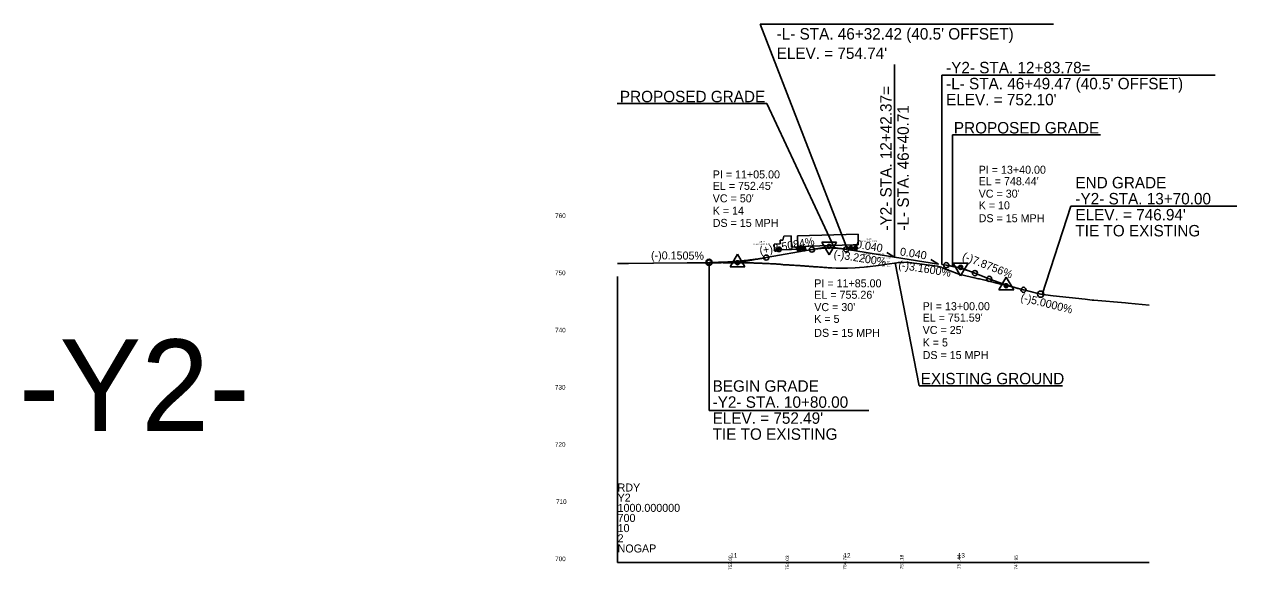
# Model space of a CAD drawing. Extents: x 1554255 to 1803987, y 659549 to 692876.
# Drawn here: x 1554284 to 1555344, y 690303 to 690780 of the extents above; entities that cross this region are included whole.
import ezdxf

# ---------------------------------------------------------------- set-up
doc = ezdxf.new("R2010")
doc.units = 0
for name, color, linetype in [('Default', 7, 'Continuous'), ('Exist Profile Cell', 7, 'Continuous'), ('Exist Vertical Profile Ground Line', 7, 'Continuous'), ('Exist Vertical Profile Vertical Axis Label', 7, 'Continuous'), ('Prop PFL Text', 7, 'Continuous'), ('Prop PFL VPI Symbol CELL', 7, 'Continuous'), ('Prop Vertical Profile Curve Label', 7, 'Continuous'), ('Prop Vertical Profile Grade', 7, 'Continuous'), ('Prop Vertical Profile Grade Label', 7, 'Continuous'), ('Prop Vertical Profile Strip Grade', 7, 'Continuous'), ('Prop VPI Label', 7, 'Continuous'), ('Scratch_Level_0', 7, 'Continuous')]:
    doc.layers.add(name, color=color, linetype=linetype)

msp = doc.modelspace()

# ---------------------------------------------------------------- linework, layer by layer
at = {"layer": 'Exist Profile Cell'}
for q in [(1554802.9, 690559.3), (1555267.8, 690309.3), (1554802.9, 690309.3)]:
    msp.add_line((1554802.9, 690309.3), q, dxfattribs=at)
at = {"layer": 'Exist Vertical Profile Ground Line'}
msp.add_lwpolyline([(1554802.9, 690570.7), (1554811.8, 690570.7), (1554812.3, 690570.7), (1554833.8, 690571), (1554834.2, 690571), (1554863.6, 690571.3), (1554864.4, 690571.3), (1554871.1, 690571.3), (1554878.4, 690571.3), (1554879.3, 690571.4), (1554880.3, 690571.4), (1554881.2, 690571.4), (1554882.2, 690571.4), (1554883.1, 690571.4), (1554884.1, 690571.4), (1554885, 690571.4), (1554886, 690571.4), (1554886.9, 690571.4), (1554887.9, 690571.4), (1554888.8, 690571.4), (1554889.8, 690571.4), (1554890.7, 690571.4), (1554891.7, 690571.4), (1554892.7, 690571.4), (1554893.6, 690571.4), (1554894.6, 690571.5), (1554895.5, 690571.4), (1554896.5, 690571.4), (1554897.4, 690571.4), (1554898.4, 690571.4), (1554899.3, 690571.4), (1554900.3, 690571.4), (1554901.2, 690571.4), (1554902.2, 690571.4), (1554903.1, 690571.4), (1554904.1, 690571.4), (1554905, 690571.4), (1554906, 690571.4), (1554906.9, 690571.4), (1554907.9, 690571.4), (1554908.8, 690571.4), (1554909.8, 690571.4), (1554910.8, 690571.4), (1554911.7, 690571.4), (1554912.7, 690571.4), (1554913.6, 690571.4), (1554914.6, 690571.4), (1554914.9, 690571.4), (1554915.5, 690571.3), (1554916.5, 690571.3), (1554917.4, 690571.3), (1554918.4, 690571.3), (1554919.3, 690571.3), (1554920.3, 690571.2), (1554920.6, 690571.2), (1554921.5, 690571.2), (1554922.2, 690571.1), (1554923.1, 690571.1), (1554924.1, 690571.1), (1554925, 690571), (1554926, 690571), (1554927, 690571), (1554927.9, 690570.9), (1554928.9, 690570.9), (1554929.8, 690570.8), (1554930.8, 690570.8), (1554931.7, 690570.8), (1554932.7, 690570.7), (1554933.6, 690570.7), (1554934.6, 690570.6), (1554935.5, 690570.6), (1554936.5, 690570.5), (1554937.4, 690570.5), (1554938.4, 690570.4), (1554939.3, 690570.4), (1554940.3, 690570.3), (1554941.2, 690570.3), (1554942.2, 690570.2), (1554943.1, 690570.1), (1554944.1, 690570.1), (1554945.1, 690570), (1554946, 690569.9), (1554946.5, 690569.8), (1554947, 690569.8), (1554947.9, 690569.7), (1554948.9, 690569.6), (1554949.2, 690569.6), (1554949.8, 690569.6), (1554950.8, 690569.5), (1554951.7, 690569.5), (1554952.7, 690569.5), (1554953.6, 690569.4), (1554954.6, 690569.4), (1554955.5, 690569.3), (1554956.5, 690569.3), (1554957.4, 690569.2), (1554958.4, 690569.1), (1554959.3, 690569.1), (1554960.3, 690569), (1554961.3, 690569), (1554962.2, 690568.9), (1554963.2, 690568.8), (1554964.1, 690568.8), (1554965.1, 690568.7), (1554966, 690568.6), (1554967, 690568.5), (1554967.9, 690568.5), (1554968.9, 690568.4), (1554969.8, 690568.3), (1554970.8, 690568.2), (1554971.2, 690568.1), (1554971.7, 690568.1), (1554972.7, 690568), (1554973.6, 690568), (1554974.6, 690567.9), (1554975.1, 690567.9), (1554975.5, 690567.8), (1554976.5, 690567.8), (1554977.4, 690567.7), (1554978.4, 690567.7), (1554979.4, 690567.6), (1554980.3, 690567.5), (1554981.3, 690567.5), (1554982.2, 690567.4), (1554983.2, 690567.3), (1554984.1, 690567.2), (1554985.1, 690567.2), (1554986, 690567.1), (1554987, 690567), (1554987.9, 690567), (1554990.2, 690566.8), (1554994, 690566.7), (1554999.4, 690566.6), (1555004, 690566.7), (1555010.7, 690566.9), (1555014.4, 690567.1), (1555018.6, 690567.4), (1555021.5, 690567.7), (1555031.2, 690569.1), (1555034.5, 690569.6), (1555036.2, 690569.9), (1555045.2, 690571.1), (1555047, 690571.3), (1555048.3, 690571.5), (1555053.3, 690571.6), (1555056.5, 690571.8), (1555056.9, 690571.7), (1555057.8, 690571.6), (1555082.8, 690568.5), (1555086.1, 690567.4), (1555086.8, 690567), (1555093.9, 690564.4), (1555099.9, 690562), (1555101.4, 690561.4), (1555117.3, 690557.6), (1555118.5, 690557.4), (1555119.3, 690557.3), (1555143.7, 690551.2), (1555145.7, 690550.8), (1555174.3, 690543.6), (1555174.8, 690543.5), (1555177, 690543.3), (1555183.9, 690542.5), (1555211.7, 690539.4), (1555213.9, 690539.2), (1555217.9, 690538.8), (1555219.4, 690538.6), (1555247.2, 690536.2), (1555249.4, 690536), (1555267.8, 690534.4)], dxfattribs=at)
at = {"layer": 'Prop PFL Text'}
for p, q in [((1554927.7, 690779.9), (1555184, 690779.9)), ((1555003.9, 690583), (1554927.7, 690779.9)), ((1555045.2, 690576.4), (1555045.2, 690744.6)), ((1555325.4, 690735.3), (1555086.6, 690735.3)), ((1555086.6, 690569.8), (1555086.6, 690735.3)), ((1554933.3, 690710.5), (1554802.6, 690710.5)), ((1554992.6, 690584.2), (1554933.3, 690710.5)), ((1555225.3, 690683.2), (1555095.7, 690683.2)), ((1555095.7, 690568.2), (1555095.7, 690683.2)), ((1555174.3, 690543.6), (1555199.3, 690620.7)), ((1555344.4, 690620.7), (1555199.3, 690620.7)), ((1554882.9, 690571.7), (1554882.9, 690442.2)), ((1555045.6, 690571.2), (1555066.7, 690463.9)), ((1555192, 690463.9), (1555066.7, 690463.9)), ((1554882.9, 690442.2), (1555022.5, 690442.2))]:
    msp.add_line(p, q, dxfattribs=at)
at = {"layer": 'Prop PFL VPI Symbol CELL'}
for p, q in [((1554987.9, 690578.2), (1554981.4, 690589.4)), ((1554994.4, 690589.4), (1554981.4, 690589.4)), ((1554987.9, 690578.2), (1554994.4, 690589.4)), ((1554907.8, 690578.9), (1554901.4, 690567.7)), ((1554907.8, 690578.9), (1554914.3, 690567.7)), ((1555102.9, 690559.8), (1555096.4, 690571)), ((1555109.4, 690571), (1555096.4, 690571)), ((1555102.9, 690559.8), (1555109.4, 690571)), ((1554901.4, 690567.7), (1554914.3, 690567.7)), ((1555142.8, 690558.8), (1555136.4, 690547.6)), ((1555142.8, 690558.8), (1555149.3, 690547.6)), ((1555136.4, 690547.6), (1555149.3, 690547.6))]:
    msp.add_line(p, q, dxfattribs=at)
for centre, radius in [((1554987.9, 690585.7), 1.75), ((1554987.9, 690585.7), 1.2), ((1554907.8, 690571.4), 1.75), ((1554907.8, 690571.4), 1.2), ((1555102.9, 690567.3), 1.75), ((1555102.9, 690567.3), 1.2), ((1555142.8, 690551.3), 1.75), ((1555142.8, 690551.3), 1.2)]:
    msp.add_circle(centre, radius, dxfattribs=at)
at = {"layer": 'Prop Vertical Profile Curve Label'}
for centre in [(1554972.9, 690582.9), (1555002.9, 690583.1), (1554882.9, 690571.7), (1554932.9, 690575.9), (1555090.4, 690569.2), (1555115.4, 690562.3), (1555127.9, 690557.3), (1555157.9, 690547.7)]:
    msp.add_circle(centre, 2.25, dxfattribs=at)
at = {"layer": 'Prop Vertical Profile Grade'}
for p, q in [((1554932.9, 690575.9), (1554972.9, 690582.9)), ((1555002.9, 690583.1), (1555003.9, 690583)), ((1555086.6, 690569.8), (1555090.4, 690569.2)), ((1555115.4, 690562.3), (1555127.9, 690557.3)), ((1555157.9, 690547.7), (1555172.9, 690543.9))]:
    msp.add_line(p, q, dxfattribs=at)
for points in [[(1554972.9, 690582.9), (1554973.5, 690583), (1554974.1, 690583.1), (1554974.7, 690583.2), (1554975.3, 690583.3), (1554975.9, 690583.4), (1554976.5, 690583.5), (1554977.1, 690583.5), (1554977.7, 690583.6), (1554978.3, 690583.7), (1554978.9, 690583.8), (1554979.5, 690583.8), (1554980.1, 690583.9), (1554980.7, 690583.9), (1554981.3, 690584), (1554981.9, 690584), (1554982.5, 690584.1), (1554983.1, 690584.1), (1554983.7, 690584.1), (1554984.3, 690584.2), (1554984.9, 690584.2), (1554985.5, 690584.2), (1554986.1, 690584.2), (1554986.7, 690584.3), (1554987.3, 690584.3), (1554987.9, 690584.3), (1554988.5, 690584.3), (1554989.1, 690584.3), (1554989.7, 690584.3), (1554990.3, 690584.3), (1554990.9, 690584.2), (1554991.5, 690584.2), (1554992.1, 690584.2), (1554992.7, 690584.2), (1554993.3, 690584.1), (1554993.9, 690584.1), (1554994.5, 690584.1), (1554995.1, 690584), (1554995.7, 690584), (1554996.3, 690583.9), (1554996.9, 690583.9), (1554997.5, 690583.8), (1554998.1, 690583.8), (1554998.7, 690583.7), (1554999.3, 690583.6), (1554999.9, 690583.6), (1555000.5, 690583.5), (1555001.1, 690583.4), (1555001.7, 690583.3), (1555002.3, 690583.2), (1555002.9, 690583.1)], [(1554882.9, 690571.7), (1554883.9, 690571.7), (1554884.9, 690571.7), (1554885.9, 690571.7), (1554886.9, 690571.7), (1554887.9, 690571.7), (1554888.9, 690571.7), (1554889.9, 690571.7), (1554890.9, 690571.7), (1554891.9, 690571.8), (1554892.9, 690571.8), (1554893.9, 690571.8), (1554894.9, 690571.9), (1554895.9, 690571.9), (1554896.9, 690571.9), (1554897.9, 690572), (1554898.9, 690572), (1554899.9, 690572.1), (1554900.9, 690572.1), (1554901.9, 690572.2), (1554902.9, 690572.3), (1554903.9, 690572.3), (1554904.9, 690572.4), (1554905.9, 690572.5), (1554906.9, 690572.6), (1554907.9, 690572.6), (1554908.9, 690572.7), (1554909.9, 690572.8), (1554910.9, 690572.9), (1554911.9, 690573), (1554912.9, 690573.1), (1554913.9, 690573.2), (1554914.9, 690573.3), (1554915.9, 690573.4), (1554916.9, 690573.5), (1554917.9, 690573.7), (1554918.9, 690573.8), (1554919.9, 690573.9), (1554920.9, 690574), (1554921.9, 690574.2), (1554922.9, 690574.3), (1554923.9, 690574.5), (1554924.9, 690574.6), (1554925.9, 690574.7), (1554926.9, 690574.9), (1554927.9, 690575.1), (1554928.9, 690575.2), (1554929.9, 690575.4), (1554930.9, 690575.5), (1554931.9, 690575.7), (1554932.9, 690575.9)], [(1555090.4, 690569.2), (1555090.9, 690569.1), (1555091.4, 690569), (1555091.9, 690568.9), (1555092.4, 690568.8), (1555092.9, 690568.7), (1555093.4, 690568.7), (1555093.9, 690568.6), (1555094.4, 690568.5), (1555094.9, 690568.4), (1555095.4, 690568.3), (1555095.9, 690568.2), (1555096.4, 690568.1), (1555096.9, 690567.9), (1555097.4, 690567.8), (1555097.9, 690567.7), (1555098.4, 690567.6), (1555098.9, 690567.5), (1555099.4, 690567.4), (1555099.9, 690567.2), (1555100.4, 690567.1), (1555100.9, 690567), (1555101.4, 690566.9), (1555101.9, 690566.7), (1555102.4, 690566.6), (1555102.9, 690566.5), (1555103.4, 690566.3), (1555103.9, 690566.2), (1555104.4, 690566), (1555104.9, 690565.9), (1555105.4, 690565.7), (1555105.9, 690565.6), (1555106.4, 690565.4), (1555106.9, 690565.3), (1555107.4, 690565.1), (1555107.9, 690565), (1555108.4, 690564.8), (1555108.9, 690564.6), (1555109.4, 690564.5), (1555109.9, 690564.3), (1555110.4, 690564.1), (1555110.9, 690563.9), (1555111.4, 690563.8), (1555111.9, 690563.6), (1555112.4, 690563.4), (1555112.9, 690563.2), (1555113.4, 690563), (1555113.9, 690562.9), (1555114.4, 690562.7), (1555114.9, 690562.5), (1555115.4, 690562.3)], [(1555127.9, 690557.3), (1555128.5, 690557.1), (1555129.1, 690556.9), (1555129.7, 690556.6), (1555130.3, 690556.4), (1555130.9, 690556.2), (1555131.5, 690556), (1555132.1, 690555.7), (1555132.7, 690555.5), (1555133.3, 690555.3), (1555133.9, 690555.1), (1555134.5, 690554.9), (1555135.1, 690554.6), (1555135.7, 690554.4), (1555136.3, 690554.2), (1555136.9, 690554), (1555137.5, 690553.8), (1555138.1, 690553.6), (1555138.7, 690553.4), (1555139.3, 690553.2), (1555139.9, 690553), (1555140.5, 690552.8), (1555141.1, 690552.6), (1555141.7, 690552.4), (1555142.3, 690552.2), (1555142.9, 690552), (1555143.5, 690551.8), (1555144.1, 690551.6), (1555144.7, 690551.4), (1555145.3, 690551.2), (1555145.9, 690551), (1555146.5, 690550.9), (1555147.1, 690550.7), (1555147.7, 690550.5), (1555148.3, 690550.3), (1555148.9, 690550.1), (1555149.5, 690550), (1555150.1, 690549.8), (1555150.7, 690549.6), (1555151.3, 690549.4), (1555151.9, 690549.3), (1555152.5, 690549.1), (1555153.1, 690548.9), (1555153.7, 690548.8), (1555154.3, 690548.6), (1555154.9, 690548.5), (1555155.5, 690548.3), (1555156.1, 690548.2), (1555156.7, 690548), (1555157.3, 690547.8), (1555157.9, 690547.7)]]:
    msp.add_spline(points, degree=3, dxfattribs=at)
at = {"layer": 'Prop VPI Label'}
for p, q in [((1554972.9, 690582.9), (1554985.1, 690585.1)), ((1555002.9, 690583.1), (1554990.6, 690585.1)), ((1555006.1, 690582.6), (1555045.2, 690576.4)), ((1555045.2, 690576.4), (1555038.5, 690580.2)), ((1554882.9, 690571.7), (1554905.1, 690571.5)), ((1554932.9, 690575.9), (1554910.6, 690572)), ((1555045.2, 690576.4), (1555083.6, 690570.2)), ((1555083.6, 690570.2), (1555076.9, 690574.1)), ((1555090.4, 690569.2), (1555100.1, 690567.6)), ((1555115.4, 690562.3), (1555105.4, 690566.2)), ((1555127.9, 690557.3), (1555140.3, 690552.5)), ((1555157.9, 690547.7), (1555145.5, 690550.8))]:
    msp.add_line(p, q, dxfattribs=at)
for centre in [(1554882.9, 690571.7), (1555172.9, 690543.9)]:
    msp.add_circle(centre, 2.75, dxfattribs=at)
at = {"layer": 'Scratch_Level_0'}
for p, q in [((1554945.1, 690591.1), (1554945, 690588)), ((1554945.1, 690591.1), (1554945, 690588)), ((1554947.4, 690591.1), (1554945.1, 690591.1)), ((1554947.4, 690591.1), (1554945.1, 690591.1)), ((1554948.2, 690594.7), (1554947.4, 690591.1)), ((1554948.2, 690594.7), (1554947.4, 690591.1)), ((1554954.7, 690594.9), (1554948.2, 690594.7)), ((1554954.7, 690594.9), (1554948.2, 690594.7)), ((1554955, 690584.9), (1554954.7, 690594.9)), ((1554955, 690584.9), (1554954.7, 690594.9)), ((1555013.2, 690596.5), (1554960.2, 690595)), ((1555013.2, 690596.5), (1554960.2, 690595)), ((1554960.2, 690595), (1554960.5, 690585.5)), ((1554960.2, 690595), (1554960.5, 690585.5)), ((1555013.4, 690587), (1555013.2, 690596.5)), ((1555013.4, 690587), (1555013.2, 690596.5)), ((1554945, 690588), (1554939.9, 690587.6)), ((1554945, 690588), (1554939.9, 690587.6)), ((1554939.9, 690587.6), (1554940, 690582.5)), ((1554939.9, 690587.6), (1554940, 690582.5)), ((1554940, 690582.5), (1554941.9, 690582.5)), ((1554940, 690582.5), (1554941.9, 690582.5)), ((1554946.2, 690582.6), (1554955, 690582.9)), ((1554946.2, 690582.6), (1554955, 690582.9)), ((1554965.6, 690585.2), (1554955, 690584.9)), ((1554965.6, 690585.2), (1554955, 690584.9)), ((1554955, 690582.9), (1554965.6, 690583.2)), ((1554955, 690582.9), (1554965.6, 690583.2)), ((1554960.5, 690585.5), (1555008.9, 690586.9)), ((1554960.5, 690585.5), (1555008.9, 690586.9)), ((1554965.6, 690583.2), (1554965.6, 690585.2)), ((1554965.6, 690583.2), (1554965.6, 690585.2)), ((1555008.9, 690586.9), (1555013.4, 690587)), ((1555008.9, 690586.9), (1555013.4, 690587))]:
    msp.add_line(p, q, dxfattribs=at)
for centre, radius in [((1554944, 690582.9), 1.83), ((1554944, 690582.9), 1.83), ((1554944, 690582.9), 1.47), ((1554944, 690582.9), 1.47), ((1554944, 690582.9), 0.262), ((1554944, 690582.9), 0.262), ((1554961.4, 690583.4), 1.83), ((1554961.4, 690583.4), 1.83), ((1554961.4, 690583.4), 1.47), ((1554961.4, 690583.4), 1.47), ((1554961.4, 690583.4), 0.262), ((1554961.4, 690583.4), 0.262), ((1554965.6, 690583.5), 1.83), ((1554965.6, 690583.5), 1.83), ((1554965.6, 690583.5), 1.47), ((1554965.6, 690583.5), 1.47), ((1554965.6, 690583.5), 0.262), ((1554965.6, 690583.5), 0.262), ((1555007, 690584.1), 1.65), ((1555007, 690584.1), 1.65), ((1555007, 690584.1), 1.32), ((1555007, 690584.1), 1.32), ((1555007, 690584.1), 0.262), ((1555007, 690584.1), 0.262), ((1555011, 690584.2), 1.65), ((1555011, 690584.2), 1.65), ((1555011, 690584.2), 1.32), ((1555011, 690584.2), 1.32), ((1555011, 690584.2), 0.262), ((1555011, 690584.2), 0.262)]:
    msp.add_circle(centre, radius, dxfattribs=at)
for start, end in [(91.5652, 190.4288), (91.5652, 190.4288), (352.7015, 91.5652), (352.7015, 91.5652)]:
    msp.add_arc((1554944, 690582.9), 2.16, start, end, dxfattribs=at)

# ---------------------------------------------------------------- texts
at = {"layer": 'Default'}
for s, p in [('760', (1554748.3, 690610.5)), ('750', (1554748.2, 690560.5)), ('740', (1554748.3, 690510.5)), ('730', (1554748.1, 690460.5)), ('720', (1554748.1, 690410.5)), ('710', (1554749.1, 690360.5)), ('700', (1554748.3, 690310.5)), ('11', (1554901.5, 690313.5)), ('12', (1555000.5, 690313.5)), ('13', (1555100.5, 690313.5))]:
    msp.add_text(s, height=4, dxfattribs=at).set_placement(p)
at = {"layer": 'Exist Profile Cell'}
for s, p in [('RDY', (1554802.9, 690371.4)), ('Y2', (1554802.9, 690362.5)), ('1000.000000', (1554802.9, 690353.6)), ('700', (1554802.9, 690344.8)), ('10', (1554802.9, 690335.9)), ('2', (1554802.9, 690327)), ('NOGAP', (1554802.9, 690318.1))]:
    msp.add_text(s, height=7, dxfattribs=at).set_placement(p)
at = {"layer": 'Exist Vertical Profile Vertical Axis Label'}
msp.add_text('-Y2-', height=80, dxfattribs=at).set_placement((1554279.2, 690424.3))
at = {"layer": 'Prop PFL Text'}
for s, p in [("-L- STA. 46+32.42 (40.5' OFFSET)", (1554942, 690766.5)), ("ELEV. = 754.74'", (1554942, 690749.5)), ('BEGIN GRADE', (1554886, 690458.6)), ('-Y2- STA. 10+80.00', (1554886, 690444.6)), ("ELEV. = 752.49'", (1554886, 690430.6)), ('TIE TO EXISTING', (1554886, 690416.6))]:
    msp.add_text(s, height=10, dxfattribs=at).set_placement(p)
for s, rotation, p in [('-Y2- STA. 12+83.78=', 360, (1555090.2, 690737)), ("-L- STA. 46+49.47 (40.5' OFFSET)", 360, (1555090.2, 690723)), ('PROPOSED GRADE', 360, (1554804.9, 690711.7)), ('-Y2- STA. 12+42.37=', 90, (1555042.6, 690599.5)), ("ELEV. = 752.10'", 360, (1555090.2, 690709)), ('-L- STA. 46+40.71 ', 90, (1555057.6, 690599.5)), ('PROPOSED GRADE', 360, (1555097, 690684.4)), ('END GRADE', 360, (1555203.3, 690636.4)), ('-Y2- STA. 13+70.00', 360, (1555203.3, 690622.4)), ("ELEV. = 746.94'", 360, (1555203.3, 690608.4)), ('TIE TO EXISTING', 360, (1555203.3, 690594.4)), ('EXISTING GROUND', 360, (1555068, 690465.1))]:
    msp.add_text(s, height=10, rotation=rotation, dxfattribs=at).set_placement(p)
at = {"layer": 'Prop Vertical Profile Grade Label'}
for s, rotation, p in [('(+)3.5084%', 9.9497, (1554927.6, 690578.5)), ('0.040', 350.8539, (1555011, 690584.3)), ('(-)0.1505%', 359.5689, (1554832.1, 690574.4)), ('(-)3.2200%', 350.8539, (1554991.5, 690575.8)), ('0.040', 350.8539, (1555049.5, 690577.9)), ('(-)7.8756%', 338.5065, (1555103.7, 690574.4)), ('(-)3.1600%', 350.8539, (1555048.1, 690566.4)), ('(-)5.0000%', 345.9638, (1555154.9, 690538.1))]:
    msp.add_text(s, height=7, rotation=rotation, dxfattribs=at).set_placement(p)
at = {"layer": 'Prop Vertical Profile Strip Grade'}
for s, p in [('752.60', (1554902.9, 690302.8)), ('754.03', (1554952.9, 690302.8)), ('754.77', (1555002.9, 690303.1)), ('753.18', (1555052.9, 690303.4)), ('751.44', (1555102.9, 690303.6)), ('747.95', (1555152.9, 690303.1))]:
    msp.add_text(s, height=3, rotation=90, dxfattribs=at).set_placement(p)
at = {"layer": 'Prop VPI Label'}
for s, p in [('PI = 13+40.00', (1555118.7, 690649.2)), ('PI = 11+05.00', (1554886.1, 690645.1)), ("EL = 748.44'", (1555118.7, 690639.2)), ("EL = 752.45'", (1554886.1, 690635.1)), ("VC = 30'", (1555118.7, 690628.3)), ("VC = 50'", (1554886.1, 690624.2)), ('K = 10', (1555118.7, 690618.1)), ('K = 14', (1554886.1, 690613.4)), ('DS = 15 MPH', (1555118.7, 690606.8)), ('DS = 15 MPH', (1554886.1, 690602.7)), ('PI = 11+85.00', (1554974.9, 690549.9)), ("EL = 755.26'", (1554974.9, 690539.9)), ("VC = 30'", (1554974.9, 690529.1)), ('PI = 13+00.00', (1555069.7, 690529.9)), ("EL = 751.59'", (1555069.7, 690519.9)), ('K = 5', (1554974.9, 690518.8)), ("VC = 25'", (1555069.7, 690509.1)), ('DS = 15 MPH', (1554974.9, 690506.6)), ('K = 5', (1555069.7, 690498.2)), ('DS = 15 MPH', (1555069.7, 690487.2))]:
    msp.add_text(s, height=7, dxfattribs=at).set_placement(p)
at = {"layer": 'Scratch_Level_0'}
for s, height, rotation, p in [('WB-67', 1.2, 1.5652, (1554926.7, 690589)), ('AASHTO 2011 (US)', 1.2, 1.5846, (1555015, 690589.4)), ('WB-67', 1.2, 1.5846, (1555020.5, 690591.5)), ('AASHTO 2011 (US)', 1.2, 1.5652, (1554921.2, 690586.8)), ('(c) 2015 Transoft Solutions, Inc. All rights reserved.', 0.048, 1.5652, (1554940.1, 690580.5)), ('(c) 2015 Transoft Solutions, Inc. All rights reserved.', 0.048, 1.5846, (1555011.6, 690582.5)), ('Ground Clearance (units: ft)', 1.2, 1.5652, (1555015.3, 690578.2)), ('Part #', 1.2, 1.5652, (1555016.3, 690574.6)), ('#1', 1.2, 1.5652, (1555020.8, 690571.2)), ('Front', 1.2, 1.5652, (1555023, 690574.8)), ('1.50', 1.2, 1.5652, (1555024.1, 690571.3)), ('N/A', 1.2, 1.5652, (1555024.2, 690567.7)), ('Wheelbase', 1.2, 1.5652, (1555028.4, 690575)), ('4.00', 1.2, 1.5652, (1555033.7, 690567.9)), ('1.50', 1.2, 1.5652, (1555033.8, 690571.5)), ('Rear', 1.2, 1.5652, (1555038.1, 690575.2)), ('4.00', 1.2, 1.5652, (1555038.4, 690568)), ('N/A', 1.2, 1.5652, (1555038.5, 690571.6)), ('#2', 1.2, 1.5652, (1555020.3, 690567.6))]:
    msp.add_text(s, height=height, rotation=rotation, dxfattribs=at).set_placement(p)

doc.saveas('drawing.dxf')
